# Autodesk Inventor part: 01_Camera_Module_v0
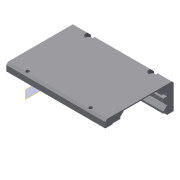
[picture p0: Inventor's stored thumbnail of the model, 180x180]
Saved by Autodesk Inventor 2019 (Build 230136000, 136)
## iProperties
Created: 2021-09
Part Number: 01_Camera_Module_v0
Material: Generisch
Document SubType Name: Modeling
Designer: Muriel
Density: 1 g/cm^3
Appearance: Vorgabe
Author: Muriel
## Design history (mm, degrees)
workplane "Arbeitsebene6"
sketch "Skizze6"
  geometry: L1 (7, 24)-(7, 1) reference; L2 (7, 1)-(8.5, 1) reference; L3 (8.5, 4)-(8.5, 1) reference; L4 (8.5, 4)-(11.3, 4) reference; L5 (11.3, 21)-(11.3, 4) reference; L6 (8.5, 21)-(11.3, 21) reference; L7 (8.5, 24)-(8.5, 21) reference; L8 (7, 24)-(8.5, 24) reference; L9 (8.5, -1)-(8.5, 1) reference; L10 (7, -1)-(8.5, -1) reference; L11 (7, -1)-(7, 1) reference; L12 (8.5, 24)-(8.5, 26) reference; L13 (7, 26)-(8.5, 26) reference; L14 (7, 24)-(7, 26) reference; L15 (12.2, -5.9)-(8.3, -5.9); L16 (3.5, 29.9)-(12.2, 29.9); L17 (12.2, 29.9)-(12.2, -5.9); L18 (7.8, 16.5)-(7.8, 25.5) reference; L19 (7.8, 25.5)-(-1.2, 25.5) reference; L20 (-1.2, 25.5)-(-1.2, 16.5) reference; L21 (-1.2, 16.5)-(7.8, 16.5) reference; L22 (3.5, 29.9)-(-1.7, 29.9); L23 (-1.7, 29.9)-(-1.7, 12); L24 (-1.7, 12)-(8.3, 12); L25 (4, 16.3)-(4, 25.7); L26 (5, 4.25)-(5, 20.75) reference; L27 (11.3, 21)-(11.3, 4) reference; L28 (8, 16.3)-(8, 25.7); L29 (8, 25.7)-(-1.4, 25.7); L30 (-1.4, 25.7)-(-1.4, 16.3); L31 (-1.4, 16.3)-(8, 16.3); L32 (4, 16.3)-(4, 25.7); L33 (7.8, 16.5)-(7.8, 25.5) reference; L34 (7.8, 25.5)-(-1.2, 25.5) reference; L35 (-1.2, 25.5)-(-1.2, 16.5) reference; L36 (-1.2, 16.5)-(7.8, 16.5) reference; L37 (-0.7, -1.5)-(8.3, -1.5) reference; L38 (8.5, 7.7)-(4.163, 7.7) reference; L39 (-0.9, 7.7)-(-0.9, -1.7) reference; L40 (8.3, -5.9)-(8.3, 4.497); L41 (8.3, -5.9)-(8.3, 12); L42 (4.166, 7.912)-(4.163, 7.7); C1 r 4 at (3.3, 21) reference; C2 r 4 at (3.3, 21) reference; 1 further point
  constraints: 36 end point, 4 horizontal, 4 parallel, 4 point on line, 2 perpendicular, 2 vertical, 8 other
  dimensions: "d41" = 13.9 distance between parallel lines of L23 L17; "d42" = 0.2 distance between parallel lines of L21 L31; "d48" = 4.2 distance between parallel lines of L29 L22 (derived); "d50" = 9 distance from line of L24 C1.centre; "d52" = 17.9 distance between parallel lines of L24 L22 (derived); "d53" = 3.9 distance between parallel lines of L17 L41; "d54" = 8.9 distance from line of L22 C2.centre; "d55" = 17.9 distance between parallel lines of L15 L24; "d58" = 8.9 distance from line of L17 C1.centre
  node "Referenz13"
  node "Referenz14"
  node "Referenz15"
  node "Referenz16"
  node "Referenz17"
  node "Referenz18"
  node "Referenz19"
  node "Referenz20"
  node "Referenz21"
  node "Referenz22"
  node "Referenz23"
workplane "Arbeitsebene7"
extrude "Extrusion6" new body sketch "Skizze6" stored distance "d43" = 2; taper "d44" = 0 deg
sketch "Skizze7"
  geometry: L1 (4.2, 0.3)-(13.6, 0.3) reference; L2 (4.2, 9.7)-(4.2, 0.3) reference; L3 (13.6, 9.7)-(4.2, 9.7) reference; L4 (13.6, 0.3)-(13.6, 9.7) reference; L5 (35.8, 10)-(17.9, 10) reference; L6 (35.8, 13.9)-(35.8, 10) reference; L7 (0, 13.9)-(35.8, 13.9) reference; L8 (0, 0)-(0, 13.9) reference; L9 (17.9, 0)-(0, 0) reference; L10 (17.9, 10)-(17.9, 0) reference; C1 r 4 at (8.9, 5) reference; 1 further point
extrude "Extrusion7" join sketch "Skizze7" distance "d56" = 2; taper "d57" = 0 deg
workplane "Arbeitsebene8"
sketch "Skizze8"
  geometry: L1 (1, 7)-(24, 7) reference; L2 (24, 7)-(24, 8.5) reference; L3 (16.25, 8.5)-(24, 8.5) reference; L4 (8.75, 8.5)-(16.25, 8.5) reference; L5 (1, 8.5)-(8.75, 8.5) reference; L6 (1, 7)-(1, 8.5) reference; L7 (26, 8.5)-(24, 8.5) reference; L8 (26, 7)-(26, 8.5) reference; L9 (26, 7)-(24, 7) reference; L10 (1, 8.5)-(-1, 8.5) reference; L11 (-1, 7)-(-1, 8.5) reference; L12 (1, 7)-(-1, 7) reference; L13 (-5.9, 12.2)-(-5.9, 8.3) reference; L14 (-5.9, 8.3)-(12, 8.3) reference; L15 (12, 8.3)-(12, -1.7) reference; L16 (12, -1.7)-(29.9, -1.7) reference; L17 (29.9, -1.7)-(29.9, 12.2) reference; L18 (29.9, 12.2)-(-5.9, 12.2) reference; L19 (25.7, 8)-(25.7, -1.4) reference; L20 (25.7, -1.4)-(16.3, -1.4) reference; L21 (16.3, -1.4)-(16.3, 8) reference; L22 (16.3, 8)-(25.7, 8) reference; L23 (29.9, 12.2)-(29.9, -1.7) reference; L24 (29.9, 12.2)-(-5.9, 12.2) reference; L25 (29.9, -1.7)-(26.4, -1.7); L26 (26.4, -1.7)-(26.4, 12.2); L27 (26.4, 12.2)-(29.9, 12.2); L28 (29.9, 12.2)-(29.9, -1.7); L29 (26.4, 12.2)-(23.4, 12.2); L30 (23.4, 12.2)-(23.4, 8.7); L31 (23.4, 8.7)-(26.4, 8.7); L32 (26.4, 8.7)-(26.4, 12.2); L33 (-5.9, 12.2)-(-5.9, 8.3) reference; L34 (-5.9, 8.3)-(12, 8.3) reference; L35 (-5.9, 12.2)-(-2, 12.2); L36 (-2, 12.2)-(-2, 8.3); L37 (-2, 8.3)-(-5.9, 8.3); L38 (-5.9, 8.3)-(-5.9, 12.2); L39 (26.4, -0.2)-(24.4, -0.2); L40 (24.4, -0.2)-(24.4, 0.8); L41 (24.4, 0.8)-(26.4, 0.8); L42 (26.4, 0.8)-(26.4, -0.2); L43 (23.4, 12.2)-(-2, 12.2); L44 (-2, 12.2)-(-2, 11.6); L45 (-2, 11.6)-(23.4, 11.6); L46 (23.4, 11.6)-(23.4, 12.2); L47 (2, 8.7)-(-2, 8.7); L48 (-2, 8.7)-(-2, 11.6); L49 (-2, 11.6)-(2, 11.6); L50 (2, 11.6)-(2, 8.7); L51 (21, 8.5)-(4, 8.5) reference; L52 (21, 8.5)-(21, 11.3) reference; L53 (4, 11.3)-(21, 11.3) reference; L54 (4, 8.5)-(4, 11.3) reference; L55 (1, 7)-(-1, 7) reference; L56 (26.4, 6.7)-(24.4, 6.7); L57 (24.4, 6.7)-(24.4, 4.7); L58 (24.4, 4.7)-(26.4, 4.7); L59 (26.4, 4.7)-(26.4, 6.7); L60 (29.9, 12.2)-(26.4, 12.2); L61 (26.4, 12.2)-(26.4, -1.7); L62 (26.4, -1.7)-(29.9, -1.7); L63 (29.9, -1.7)-(29.9, 12.2); 2 further points
  constraints: 64 end point, 16 parallel, 8 horizontal, 8 perpendicular, 5 point on line, 1 other
  dimensions: "d59" = 0.3 distance from line of L53.start L45; "d60" = 1 distance between parallel lines of L11 L48; "d61" = 0.2 distance from line of L47 L5.start; "d62" = 2 distance between parallel lines of L54 L50; "d63" = 0.2 distance between parallel lines of L7 L31; "d64" = 3 distance between parallel lines of L26 L30; "d65" = 0.4 distance between parallel lines of L26 L8; "d66" = 0.2 distance from line of point (23, -0.4) L39; "d67" = 1 distance between parallel lines of L39 L41; "d68" = 2 distance between parallel lines of L42 L40; "d69" = 2 distance of L58.end L57.end; "d70" = 2 distance of L57.end L56.end; "d71" = 0.3 distance between parallel lines of L9 L56
extrude "Extrusion8" join sketch "Skizze8" stored distance "d72" = 2; taper "d73" = 0 deg
sketch "Skizze9"
  geometry: L1 (51.8, 0)-(0, 0) reference; L2 (51.8, 0)-(51.8, 35.8) reference; L3 (0, 35.8)-(51.8, 35.8) reference; L4 (0, 0)-(0, 35.8) reference; L5 (5.1, 7.9)-(51.8, 7.9) reference; L6 (5.1, 3.5)-(51.8, 3.5) reference; L7 (5.1, 3.9)-(51.8, 3.9) reference; L8 (5.1, 32.3)-(51.8, 32.3) reference; L9 (50.05, 34.05)-(50.05, 1.75); L10 (50.05, 1.75)-(1.75, 1.75); L11 (1.75, 1.75)-(1.75, 34.05); L12 (1.75, 34.05)-(50.05, 34.05); 5 further points
  constraints: 10 end point, 4 point on line, 1 horizontal, 5 other
  dimensions: "d74" = 1.75 distance between parallel lines of L3 L12; "d75" = 11 distance of point (18.423, 34.05) point (7.423, 34.05); "d76" = 11 distance of point (29.423, 34.05) point (18.423, 34.05); "d77" = 11 distance of point (40.423, 34.05) point (29.423, 34.05)
hole "Bohrung1" sketch "Skizze9" at (7.423, 34.05), (40.423, 34.05) diameter "d78" = 1.8; stored, may be unused: countersink angle "d82" = 90 deg, drill point angle "d84" = 118 deg; dims "d79" = 6, "d80" = 4, "d81" = 2, "d83" = 12
sketch "Skizze10"
  geometry: C1 r 0.9 at (9.431, 1.75) reference; C2 r 0.9 at (42.431, 1.75) reference; 1 further point
  constraints: 2 centre point, 4 other
extrude "Extrusion9" cut sketch "Skizze10" extent not by distance; stored distance "d85" = 2; taper "d86" = 0 deg
chamfer "Fase1" distance "d87" = 1; stored, may be unused: second distance "d88" = 2, angle "d89" = 45 deg
chamfer "Fase2" distance "d90" = 1; stored, may be unused: second distance "d91" = 2, angle "d92" = 45 deg
sketch "Skizze11"
  geometry: L1 (49.8, 0.3)-(49.8, 9.7) reference; L2 (47.7, 0.3)-(47.7, 9.7) reference; C1 r 1.4 at (47.7, 5); 1 further point
  constraints: 1 centre point, 1 midpoint
  dimensions: "d93" = 2.8 diameter of C1
extrude "Extrusion10" cut sketch "Skizze11" distance "d94" = 10; taper "d95" = 0 deg
sketch "Skizze12"
  geometry: L1 (5.1, -12.4)-(5.1, -13.7) reference; L2 (5.1, -12.4)-(51.8, -12.4) reference; L3 (5.1, -14.4)-(51.8, -14.4) reference; L4 (51.8, -14.4)-(51.8, -12.4) reference; L5 (5.1, -12.4)-(51.8, -12.4) reference; L6 (5.1, -12.4)-(5.1, -13.7) reference; L7 (5.1, -14.4)-(5.1, -13.7) reference; L8 (5.1, -14.4)-(51.8, -14.4) reference; L9 (5.1, -14.4)-(9.499, -14.4); L10 (9.499, -14.4)-(9.499, -12.4); L11 (9.499, -12.4)-(5.1, -12.4); L12 (5.1, -12.4)-(5.1, -14.4); 1 further point
  constraints: 8 end point, 2 parallel, 1 horizontal, 1 perpendicular, 1 point on line
  node "Projizierte Kontur8"
workplane "Arbeitsebene9"
extrude "Extrusion11" cut sketch "Skizze12" stored distance "d96" = 2; taper "d97" = 0 deg
chamfer "Fase3" distance "d98" = 1.9; stored, may be unused: second distance "d99" = 2, angle "d100" = 45 deg
sketch "Skizze13"
  geometry: L1 (-32.3, 4.5)-(-31.3, 5.5) reference; L2 (-32.3, 1.6)-(-32.3, 4.5) reference; L3 (-28.4, 1.6)-(-32.3, 1.6) reference; L4 (-28.4, 2)-(-28.4, 1.6) reference; L5 (-24.4, 2)-(-28.4, 2) reference; L6 (-24.4, 3)-(-24.4, 2) reference; L7 (-22.5, 4.9)-(-24.4, 3) reference; L8 (-4.9, 4.9)-(-22.5, 4.9) reference; L9 (-3, 3)-(-4.9, 4.9) reference; L10 (-3, 2)-(-3, 3) reference; L11 (0, 2)-(-3, 2) reference; L12 (0, 0)-(0, 2) reference; L13 (-2, 0)-(0, 0) reference; L14 (-2, -2)-(-2, 0) reference; L15 (-1.9, -2)-(-2, -2) reference; L16 (0, -3.9)-(-1.9, -2) reference; L17 (0, -4)-(0, -3.9) reference; L18 (-1.9, -5.9)-(0, -4) reference; L19 (-2, -5.9)-(-1.9, -5.9) reference; L20 (-2, -6.9)-(-2, -5.9) reference; L21 (0, -6.9)-(-2, -6.9) reference; L22 (0, -8.4)-(0, -6.9) reference; L23 (3.5, -8.4)-(0, -8.4) reference; L24 (3.5, 4.5)-(3.5, -8.4) reference; L25 (2.5, 5.5)-(3.5, 4.5) reference; L26 (-31.3, 5.5)-(2.5, 5.5) reference; C1 r 1.4 at (1.4, -5.4); C2 r 1.4 at (1.4, 3.4); 1 further point
  constraints: 2 centre point
  dimensions: "d101" = 2.8 diameter of C1; "d102" = 2.8 diameter of C2
extrude "Extrusion12" cut sketch "Skizze13" distance "d103" = 8; taper "d104" = 0 deg
node "Volumenkörper2"
node "Projizierte Kontur5"
node "Referenz24"
node "Referenz25"
node "Referenz26"
node "Referenz27"
node "Referenz28"
node "Referenz29"
node "Referenz30"
node "Referenz31"
node "Projizierte Kontur6"
node "Referenz32"
node "Referenz33"
node "Projizierte Kontur7"
node "Projizierte Kontur9"
other parameters: "d39" = 1, "d51" = 17.4
